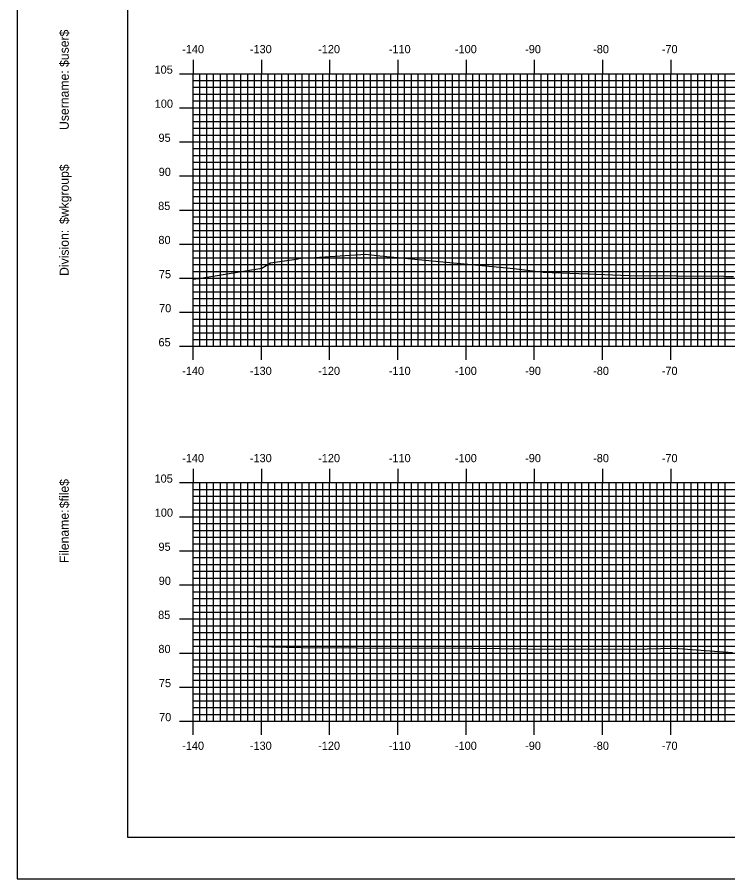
# Model space of a CAD drawing. Extents: x 857110 to 857453, y 364765 to 364985.
# Drawn here: x 857110 to 857214.2, y 364765.2 to 364891.6 of the extents above; entities that cross this region are included whole.
import ezdxf

# ---------------------------------------------------------------- set-up
doc = ezdxf.new("R2010")
doc.units = 0
for name, color, linetype in [('BORDER', 7, 'Continuous'), ('H_V ANNOTATION', 7, 'Continuous'), ('MAJOR', 7, 'Continuous'), ('MINOR', 7, 'Continuous'), ('PLOT BOUNDARY', 7, 'Continuous'), ('S_Roadway_Centerline', 7, 'Continuous')]:
    doc.layers.add(name, color=color, linetype=linetype)

msp = doc.modelspace()

# ---------------------------------------------------------------- linework, layer by layer
at = {"layer": 'BORDER'}
msp.add_lwpolyline([(857126.19, 364771.3), (857446.19, 364771.3), (857446.19, 364981.3), (857126.19, 364981.3)], close=True, dxfattribs=at)
at = {"layer": 'MAJOR'}
for p, q in [((857135.79, 364885.31), (857135.79, 364883.3)), ((857145.79, 364885.31), (857145.79, 364883.3)), ((857155.79, 364885.31), (857155.79, 364883.3)), ((857165.79, 364885.31), (857165.79, 364883.3)), ((857175.79, 364885.31), (857175.79, 364883.3)), ((857185.79, 364885.31), (857185.79, 364883.3)), ((857195.79, 364885.31), (857195.79, 364883.3)), ((857205.79, 364885.31), (857205.79, 364883.3)), ((857133.79, 364883.3), (857135.79, 364883.3)), ((857135.79, 364883.3), (857415.79, 364883.3)), ((857135.79, 364843.3), (857135.79, 364883.3)), ((857135.79, 364843.3), (857135.79, 364883.3)), ((857135.79, 364883.3), (857415.79, 364883.3)), ((857145.79, 364843.3), (857145.79, 364883.3)), ((857155.79, 364843.3), (857155.79, 364883.3)), ((857165.79, 364843.3), (857165.79, 364883.3)), ((857175.79, 364843.3), (857175.79, 364883.3)), ((857185.79, 364843.3), (857185.79, 364883.3)), ((857195.79, 364843.3), (857195.79, 364883.3)), ((857205.79, 364843.3), (857205.79, 364883.3)), ((857133.79, 364878.3), (857135.79, 364878.3)), ((857135.79, 364878.3), (857415.79, 364878.3)), ((857133.79, 364873.3), (857135.79, 364873.3)), ((857135.79, 364873.3), (857415.79, 364873.3)), ((857133.79, 364868.3), (857135.79, 364868.3)), ((857135.79, 364868.3), (857415.79, 364868.3)), ((857133.79, 364863.3), (857135.79, 364863.3)), ((857135.79, 364863.3), (857415.79, 364863.3)), ((857133.79, 364858.3), (857135.79, 364858.3)), ((857135.79, 364858.3), (857415.79, 364858.3)), ((857133.79, 364853.3), (857135.79, 364853.3)), ((857135.79, 364853.3), (857415.79, 364853.3)), ((857133.79, 364848.3), (857135.79, 364848.3)), ((857135.79, 364848.3), (857415.79, 364848.3)), ((857133.79, 364843.3), (857135.79, 364843.3)), ((857135.79, 364843.3), (857415.79, 364843.3)), ((857135.79, 364843.3), (857415.79, 364843.3)), ((857135.79, 364841.3), (857135.79, 364843.3)), ((857145.79, 364841.3), (857145.79, 364843.3)), ((857155.79, 364841.3), (857155.79, 364843.3)), ((857165.79, 364841.3), (857165.79, 364843.3)), ((857175.79, 364841.3), (857175.79, 364843.3)), ((857185.79, 364841.3), (857185.79, 364843.3)), ((857195.79, 364841.3), (857195.79, 364843.3)), ((857205.79, 364841.3), (857205.79, 364843.3)), ((857135.79, 364825.31), (857135.79, 364823.3)), ((857145.79, 364825.31), (857145.79, 364823.3)), ((857155.79, 364825.31), (857155.79, 364823.3)), ((857165.79, 364825.31), (857165.79, 364823.3)), ((857175.79, 364825.31), (857175.79, 364823.3)), ((857185.79, 364825.31), (857185.79, 364823.3)), ((857195.79, 364825.31), (857195.79, 364823.3)), ((857205.79, 364825.31), (857205.79, 364823.3)), ((857133.79, 364823.3), (857135.79, 364823.3)), ((857135.79, 364823.3), (857415.79, 364823.3)), ((857135.79, 364788.3), (857135.79, 364823.3)), ((857135.79, 364788.3), (857135.79, 364823.3)), ((857135.79, 364823.3), (857415.79, 364823.3)), ((857145.79, 364788.3), (857145.79, 364823.3)), ((857155.79, 364788.3), (857155.79, 364823.3)), ((857165.79, 364788.3), (857165.79, 364823.3)), ((857175.79, 364788.3), (857175.79, 364823.3)), ((857185.79, 364788.3), (857185.79, 364823.3)), ((857195.79, 364788.3), (857195.79, 364823.3)), ((857205.79, 364788.3), (857205.79, 364823.3)), ((857133.79, 364818.3), (857135.79, 364818.3)), ((857135.79, 364818.3), (857415.79, 364818.3)), ((857133.79, 364813.3), (857135.79, 364813.3)), ((857135.79, 364813.3), (857415.79, 364813.3)), ((857133.79, 364808.3), (857135.79, 364808.3)), ((857135.79, 364808.3), (857415.79, 364808.3)), ((857133.79, 364803.3), (857135.79, 364803.3)), ((857135.79, 364803.3), (857415.79, 364803.3)), ((857133.79, 364798.3), (857135.79, 364798.3)), ((857135.79, 364798.3), (857415.79, 364798.3)), ((857133.79, 364793.3), (857135.79, 364793.3)), ((857135.79, 364793.3), (857415.79, 364793.3)), ((857133.79, 364788.3), (857135.79, 364788.3)), ((857135.79, 364788.3), (857415.79, 364788.3)), ((857135.79, 364788.3), (857415.79, 364788.3)), ((857135.79, 364786.3), (857135.79, 364788.3)), ((857145.79, 364786.3), (857145.79, 364788.3)), ((857155.79, 364786.3), (857155.79, 364788.3)), ((857165.79, 364786.3), (857165.79, 364788.3)), ((857175.79, 364786.3), (857175.79, 364788.3)), ((857185.79, 364786.3), (857185.79, 364788.3)), ((857195.79, 364786.3), (857195.79, 364788.3)), ((857205.79, 364786.3), (857205.79, 364788.3))]:
    msp.add_line(p, q, dxfattribs=at)
at = {"layer": 'MINOR'}
for p, q in [((857136.79, 364843.3), (857136.79, 364883.3)), ((857137.79, 364843.3), (857137.79, 364883.3)), ((857138.79, 364843.3), (857138.79, 364883.3)), ((857139.79, 364843.3), (857139.79, 364883.3)), ((857140.79, 364843.3), (857140.79, 364883.3)), ((857141.79, 364843.3), (857141.79, 364883.3)), ((857142.79, 364843.3), (857142.79, 364883.3)), ((857143.79, 364843.3), (857143.79, 364883.3)), ((857144.79, 364843.3), (857144.79, 364883.3)), ((857146.79, 364843.3), (857146.79, 364883.3)), ((857147.79, 364843.3), (857147.79, 364883.3)), ((857148.79, 364843.3), (857148.79, 364883.3)), ((857149.79, 364843.3), (857149.79, 364883.3)), ((857150.79, 364843.3), (857150.79, 364883.3)), ((857151.79, 364843.3), (857151.79, 364883.3)), ((857152.79, 364843.3), (857152.79, 364883.3)), ((857153.79, 364843.3), (857153.79, 364883.3)), ((857154.79, 364843.3), (857154.79, 364883.3)), ((857156.79, 364843.3), (857156.79, 364883.3)), ((857157.79, 364843.3), (857157.79, 364883.3)), ((857158.79, 364843.3), (857158.79, 364883.3)), ((857159.79, 364843.3), (857159.79, 364883.3)), ((857160.79, 364843.3), (857160.79, 364883.3)), ((857161.79, 364843.3), (857161.79, 364883.3)), ((857162.79, 364843.3), (857162.79, 364883.3)), ((857163.79, 364843.3), (857163.79, 364883.3)), ((857164.79, 364843.3), (857164.79, 364883.3)), ((857166.79, 364843.3), (857166.79, 364883.3)), ((857167.79, 364843.3), (857167.79, 364883.3)), ((857168.79, 364843.3), (857168.79, 364883.3)), ((857169.79, 364843.3), (857169.79, 364883.3)), ((857170.79, 364843.3), (857170.79, 364883.3)), ((857171.79, 364843.3), (857171.79, 364883.3)), ((857172.79, 364843.3), (857172.79, 364883.3)), ((857173.79, 364843.3), (857173.79, 364883.3)), ((857174.79, 364843.3), (857174.79, 364883.3)), ((857176.79, 364843.3), (857176.79, 364883.3)), ((857177.79, 364843.3), (857177.79, 364883.3)), ((857178.79, 364843.3), (857178.79, 364883.3)), ((857179.79, 364843.3), (857179.79, 364883.3)), ((857180.79, 364843.3), (857180.79, 364883.3)), ((857181.79, 364843.3), (857181.79, 364883.3)), ((857182.79, 364843.3), (857182.79, 364883.3)), ((857183.79, 364843.3), (857183.79, 364883.3)), ((857184.79, 364843.3), (857184.79, 364883.3)), ((857186.79, 364843.3), (857186.79, 364883.3)), ((857187.79, 364843.3), (857187.79, 364883.3)), ((857188.79, 364843.3), (857188.79, 364883.3)), ((857189.79, 364843.3), (857189.79, 364883.3)), ((857190.79, 364843.3), (857190.79, 364883.3)), ((857191.79, 364843.3), (857191.79, 364883.3)), ((857192.79, 364843.3), (857192.79, 364883.3)), ((857193.79, 364843.3), (857193.79, 364883.3)), ((857194.79, 364843.3), (857194.79, 364883.3)), ((857196.79, 364843.3), (857196.79, 364883.3)), ((857197.79, 364843.3), (857197.79, 364883.3)), ((857198.79, 364843.3), (857198.79, 364883.3)), ((857199.79, 364843.3), (857199.79, 364883.3)), ((857200.79, 364843.3), (857200.79, 364883.3)), ((857201.79, 364843.3), (857201.79, 364883.3)), ((857202.79, 364843.3), (857202.79, 364883.3)), ((857203.79, 364843.3), (857203.79, 364883.3)), ((857204.79, 364843.3), (857204.79, 364883.3)), ((857206.79, 364843.3), (857206.79, 364883.3)), ((857207.79, 364843.3), (857207.79, 364883.3)), ((857208.79, 364843.3), (857208.79, 364883.3)), ((857209.79, 364843.3), (857209.79, 364883.3)), ((857210.79, 364843.3), (857210.79, 364883.3)), ((857211.79, 364843.3), (857211.79, 364883.3)), ((857212.79, 364843.3), (857212.79, 364883.3)), ((857213.79, 364843.3), (857213.79, 364883.3)), ((857135.79, 364882.3), (857415.79, 364882.3)), ((857135.79, 364882.3), (857137.8, 364882.3)), ((857135.79, 364881.3), (857415.79, 364881.3)), ((857135.79, 364881.3), (857137.8, 364881.3)), ((857135.79, 364880.3), (857415.79, 364880.3)), ((857135.79, 364880.3), (857137.8, 364880.3)), ((857135.79, 364879.3), (857415.79, 364879.3)), ((857135.79, 364879.3), (857137.8, 364879.3)), ((857135.79, 364877.3), (857415.79, 364877.3)), ((857135.79, 364877.3), (857137.8, 364877.3)), ((857135.79, 364876.3), (857415.79, 364876.3)), ((857135.79, 364876.3), (857137.8, 364876.3)), ((857135.79, 364875.3), (857415.79, 364875.3)), ((857135.79, 364875.3), (857137.8, 364875.3)), ((857135.79, 364874.3), (857415.79, 364874.3)), ((857135.79, 364874.3), (857137.8, 364874.3)), ((857135.79, 364872.3), (857415.79, 364872.3)), ((857135.79, 364872.3), (857137.8, 364872.3)), ((857135.79, 364871.3), (857415.79, 364871.3)), ((857135.79, 364871.3), (857137.8, 364871.3)), ((857135.79, 364870.3), (857415.79, 364870.3)), ((857135.79, 364870.3), (857137.8, 364870.3)), ((857135.79, 364869.3), (857415.79, 364869.3)), ((857135.79, 364869.3), (857137.8, 364869.3)), ((857135.79, 364867.3), (857415.79, 364867.3)), ((857135.79, 364867.3), (857137.8, 364867.3)), ((857135.79, 364866.3), (857415.79, 364866.3)), ((857135.79, 364866.3), (857137.8, 364866.3)), ((857135.79, 364865.3), (857415.79, 364865.3)), ((857135.79, 364865.3), (857137.8, 364865.3)), ((857135.79, 364864.3), (857415.79, 364864.3)), ((857135.79, 364864.3), (857137.8, 364864.3)), ((857135.79, 364862.3), (857415.79, 364862.3)), ((857135.79, 364862.3), (857137.8, 364862.3)), ((857135.79, 364861.3), (857415.79, 364861.3)), ((857135.79, 364861.3), (857137.8, 364861.3)), ((857135.79, 364860.3), (857415.79, 364860.3)), ((857135.79, 364860.3), (857137.8, 364860.3)), ((857135.79, 364859.3), (857415.79, 364859.3)), ((857135.79, 364859.3), (857137.8, 364859.3)), ((857135.79, 364857.3), (857415.79, 364857.3)), ((857135.79, 364857.3), (857137.8, 364857.3)), ((857135.79, 364856.3), (857415.79, 364856.3)), ((857135.79, 364856.3), (857137.8, 364856.3)), ((857135.79, 364855.3), (857415.79, 364855.3)), ((857135.79, 364855.3), (857137.8, 364855.3)), ((857135.79, 364854.3), (857415.79, 364854.3)), ((857135.79, 364854.3), (857137.8, 364854.3)), ((857135.79, 364852.3), (857415.79, 364852.3)), ((857135.79, 364852.3), (857137.8, 364852.3)), ((857135.79, 364851.3), (857415.79, 364851.3)), ((857135.79, 364851.3), (857137.8, 364851.3)), ((857135.79, 364850.3), (857415.79, 364850.3)), ((857135.79, 364850.3), (857137.8, 364850.3)), ((857135.79, 364849.3), (857415.79, 364849.3)), ((857135.79, 364849.3), (857137.8, 364849.3)), ((857135.79, 364847.3), (857415.79, 364847.3)), ((857135.79, 364847.3), (857137.8, 364847.3)), ((857135.79, 364846.3), (857415.79, 364846.3)), ((857135.79, 364846.3), (857137.8, 364846.3)), ((857135.79, 364845.3), (857415.79, 364845.3)), ((857135.79, 364845.3), (857137.8, 364845.3)), ((857135.79, 364844.3), (857415.79, 364844.3)), ((857135.79, 364844.3), (857137.8, 364844.3)), ((857135.79, 364822.3), (857415.79, 364822.3)), ((857135.79, 364822.3), (857137.8, 364822.3)), ((857136.79, 364788.3), (857136.79, 364823.3)), ((857137.79, 364788.3), (857137.79, 364823.3)), ((857138.79, 364788.3), (857138.79, 364823.3)), ((857139.79, 364788.3), (857139.79, 364823.3)), ((857140.79, 364788.3), (857140.79, 364823.3)), ((857141.79, 364788.3), (857141.79, 364823.3)), ((857142.79, 364788.3), (857142.79, 364823.3)), ((857143.79, 364788.3), (857143.79, 364823.3)), ((857144.79, 364788.3), (857144.79, 364823.3)), ((857146.79, 364788.3), (857146.79, 364823.3)), ((857147.79, 364788.3), (857147.79, 364823.3)), ((857148.79, 364788.3), (857148.79, 364823.3)), ((857149.79, 364788.3), (857149.79, 364823.3)), ((857150.79, 364788.3), (857150.79, 364823.3)), ((857151.79, 364788.3), (857151.79, 364823.3)), ((857152.79, 364788.3), (857152.79, 364823.3)), ((857153.79, 364788.3), (857153.79, 364823.3)), ((857154.79, 364788.3), (857154.79, 364823.3)), ((857156.79, 364788.3), (857156.79, 364823.3)), ((857157.79, 364788.3), (857157.79, 364823.3)), ((857158.79, 364788.3), (857158.79, 364823.3)), ((857159.79, 364788.3), (857159.79, 364823.3)), ((857160.79, 364788.3), (857160.79, 364823.3)), ((857161.79, 364788.3), (857161.79, 364823.3)), ((857162.79, 364788.3), (857162.79, 364823.3)), ((857163.79, 364788.3), (857163.79, 364823.3)), ((857164.79, 364788.3), (857164.79, 364823.3)), ((857166.79, 364788.3), (857166.79, 364823.3)), ((857167.79, 364788.3), (857167.79, 364823.3)), ((857168.79, 364788.3), (857168.79, 364823.3)), ((857169.79, 364788.3), (857169.79, 364823.3)), ((857170.79, 364788.3), (857170.79, 364823.3)), ((857171.79, 364788.3), (857171.79, 364823.3)), ((857172.79, 364788.3), (857172.79, 364823.3)), ((857173.79, 364788.3), (857173.79, 364823.3)), ((857174.79, 364788.3), (857174.79, 364823.3)), ((857176.79, 364788.3), (857176.79, 364823.3)), ((857177.79, 364788.3), (857177.79, 364823.3)), ((857178.79, 364788.3), (857178.79, 364823.3)), ((857179.79, 364788.3), (857179.79, 364823.3)), ((857180.79, 364788.3), (857180.79, 364823.3)), ((857181.79, 364788.3), (857181.79, 364823.3)), ((857182.79, 364788.3), (857182.79, 364823.3)), ((857183.79, 364788.3), (857183.79, 364823.3)), ((857184.79, 364788.3), (857184.79, 364823.3)), ((857186.79, 364788.3), (857186.79, 364823.3)), ((857187.79, 364788.3), (857187.79, 364823.3)), ((857188.79, 364788.3), (857188.79, 364823.3)), ((857189.79, 364788.3), (857189.79, 364823.3)), ((857190.79, 364788.3), (857190.79, 364823.3)), ((857191.79, 364788.3), (857191.79, 364823.3)), ((857192.79, 364788.3), (857192.79, 364823.3)), ((857193.79, 364788.3), (857193.79, 364823.3)), ((857194.79, 364788.3), (857194.79, 364823.3)), ((857196.79, 364788.3), (857196.79, 364823.3)), ((857197.79, 364788.3), (857197.79, 364823.3)), ((857198.79, 364788.3), (857198.79, 364823.3)), ((857199.79, 364788.3), (857199.79, 364823.3)), ((857200.79, 364788.3), (857200.79, 364823.3)), ((857201.79, 364788.3), (857201.79, 364823.3)), ((857202.79, 364788.3), (857202.79, 364823.3)), ((857203.79, 364788.3), (857203.79, 364823.3)), ((857204.79, 364788.3), (857204.79, 364823.3)), ((857206.79, 364788.3), (857206.79, 364823.3)), ((857207.79, 364788.3), (857207.79, 364823.3)), ((857208.79, 364788.3), (857208.79, 364823.3)), ((857209.79, 364788.3), (857209.79, 364823.3)), ((857210.79, 364788.3), (857210.79, 364823.3)), ((857211.79, 364788.3), (857211.79, 364823.3)), ((857212.79, 364788.3), (857212.79, 364823.3)), ((857213.79, 364788.3), (857213.79, 364823.3)), ((857135.79, 364821.3), (857415.79, 364821.3)), ((857135.79, 364821.3), (857137.8, 364821.3)), ((857135.79, 364820.3), (857415.79, 364820.3)), ((857135.79, 364820.3), (857137.8, 364820.3)), ((857135.79, 364819.3), (857415.79, 364819.3)), ((857135.79, 364819.3), (857137.8, 364819.3)), ((857135.79, 364817.3), (857415.79, 364817.3)), ((857135.79, 364817.3), (857137.8, 364817.3)), ((857135.79, 364816.3), (857415.79, 364816.3)), ((857135.79, 364816.3), (857137.8, 364816.3)), ((857135.79, 364815.3), (857415.79, 364815.3)), ((857135.79, 364815.3), (857137.8, 364815.3)), ((857135.79, 364814.3), (857415.79, 364814.3)), ((857135.79, 364814.3), (857137.8, 364814.3)), ((857135.79, 364812.3), (857415.79, 364812.3)), ((857135.79, 364812.3), (857137.8, 364812.3)), ((857135.79, 364811.3), (857137.8, 364811.3)), ((857135.79, 364811.3), (857415.79, 364811.3)), ((857135.79, 364810.3), (857137.8, 364810.3)), ((857135.79, 364810.3), (857415.79, 364810.3)), ((857135.79, 364809.3), (857415.79, 364809.3)), ((857135.79, 364809.3), (857137.8, 364809.3)), ((857135.79, 364807.3), (857415.79, 364807.3)), ((857135.79, 364807.3), (857137.8, 364807.3)), ((857135.79, 364806.3), (857415.79, 364806.3)), ((857135.79, 364806.3), (857137.8, 364806.3)), ((857135.79, 364805.3), (857415.79, 364805.3)), ((857135.79, 364805.3), (857137.8, 364805.3)), ((857135.79, 364804.3), (857415.79, 364804.3)), ((857135.79, 364804.3), (857137.8, 364804.3)), ((857135.79, 364802.3), (857415.79, 364802.3)), ((857135.79, 364802.3), (857137.8, 364802.3)), ((857135.79, 364801.3), (857415.79, 364801.3)), ((857135.79, 364801.3), (857137.8, 364801.3)), ((857135.79, 364800.3), (857415.79, 364800.3)), ((857135.79, 364800.3), (857137.8, 364800.3)), ((857135.79, 364799.3), (857415.79, 364799.3)), ((857135.79, 364799.3), (857137.8, 364799.3)), ((857135.79, 364797.3), (857415.79, 364797.3)), ((857135.79, 364797.3), (857137.8, 364797.3)), ((857135.79, 364796.3), (857415.79, 364796.3)), ((857135.79, 364796.3), (857137.8, 364796.3)), ((857135.79, 364795.3), (857415.79, 364795.3)), ((857135.79, 364795.3), (857137.8, 364795.3)), ((857135.79, 364794.3), (857415.79, 364794.3)), ((857135.79, 364794.3), (857137.8, 364794.3)), ((857135.79, 364792.3), (857415.79, 364792.3)), ((857135.79, 364792.3), (857137.8, 364792.3)), ((857135.79, 364791.3), (857415.79, 364791.3)), ((857135.79, 364791.3), (857137.8, 364791.3)), ((857135.79, 364790.3), (857415.79, 364790.3)), ((857135.79, 364790.3), (857137.8, 364790.3)), ((857135.79, 364789.3), (857415.79, 364789.3)), ((857135.79, 364789.3), (857137.8, 364789.3))]:
    msp.add_line(p, q, dxfattribs=at)
at = {"layer": 'PLOT BOUNDARY'}
msp.add_lwpolyline([(857110.01, 364765.18), (857450.01, 364765.18), (857450.01, 364985.18), (857110.01, 364985.18)], close=True, dxfattribs=at)
at = {"layer": 'S_Roadway_Centerline'}
for points in [[(857135.79, 364853.15), (857136.61, 364853.26), (857136.85, 364853.28), (857137.23, 364853.34), (857145.84, 364854.78), (857147.11, 364855.54), (857150.89, 364856.11), (857151.57, 364856.24), (857153.56, 364856.34), (857161.12, 364856.82), (857163.17, 364856.58), (857172.37, 364855.72), (857182.8, 364854.72), (857187.11, 364854.19), (857193.63, 364853.92), (857199.71, 364853.68), (857213.59, 364853.58), (857213.93, 364853.55), (857215.01, 364853.53)], [(857135.79, 364799.36), (857142.95, 364799.3), (857151.64, 364799.13), (857159.77, 364799.08), (857165.97, 364799.01), (857172.59, 364799.08), (857184.77, 364798.94), (857200.37, 364798.89), (857206.28, 364799.02), (857214.84, 364798.4)]]:
    msp.add_lwpolyline(points, dxfattribs=at)

# ---------------------------------------------------------------- texts
at = {"layer": 'BORDER'}
for s, p in [('$user$', (857117.56, 364884.29)), ('Username:', (857117.56, 364875.04)), ('$wkgroup$', (857117.56, 364861.24)), ('Division:', (857117.56, 364853.63)), ('$file$', (857117.56, 364819.55)), ('Filename:', (857117.56, 364811.5))]:
    msp.add_text(s, height=1.339, rotation=90, dxfattribs=at).set_placement(p)
at = {"layer": 'H_V ANNOTATION'}
for s, p in [('-140', (857134.18, 364886.3)), ('-130', (857144.1, 364886.3)), ('-120', (857154.11, 364886.3)), ('-110', (857164.46, 364886.3)), ('-100', (857174.16, 364886.3)), ('-90', (857184.45, 364886.3)), ('-80', (857194.42, 364886.3)), ('-70', (857204.48, 364886.3)), ('105', (857130.13, 364883.3)), ('100', (857130.16, 364878.3)), ('95', (857130.71, 364873.3)), ('90', (857130.74, 364868.3)), ('85', (857130.66, 364863.3)), ('80', (857130.7, 364858.3)), ('75', (857130.77, 364853.3)), ('70', (857130.8, 364848.3)), ('65', (857130.71, 364843.3)), ('-140', (857134.18, 364839.1)), ('-130', (857144.1, 364839.1)), ('-120', (857154.11, 364839.1)), ('-110', (857164.46, 364839.1)), ('-100', (857174.16, 364839.1)), ('-90', (857184.45, 364839.1)), ('-80', (857194.42, 364839.1)), ('-70', (857204.48, 364839.1)), ('-140', (857134.18, 364826.3)), ('-130', (857144.1, 364826.3)), ('-120', (857154.11, 364826.3)), ('-110', (857164.46, 364826.3)), ('-100', (857174.16, 364826.3)), ('-90', (857184.45, 364826.3)), ('-80', (857194.42, 364826.3)), ('-70', (857204.48, 364826.3)), ('105', (857130.13, 364823.3)), ('100', (857130.16, 364818.3)), ('95', (857130.71, 364813.3)), ('90', (857130.74, 364808.3)), ('85', (857130.66, 364803.3)), ('80', (857130.7, 364798.3)), ('75', (857130.77, 364793.3)), ('70', (857130.8, 364788.3)), ('-140', (857134.18, 364784.1)), ('-130', (857144.1, 364784.1)), ('-120', (857154.11, 364784.1)), ('-110', (857164.46, 364784.1)), ('-100', (857174.16, 364784.1)), ('-90', (857184.45, 364784.1)), ('-80', (857194.42, 364784.1)), ('-70', (857204.48, 364784.1))]:
    msp.add_text(s, height=1.2, dxfattribs=at).set_placement(p)
at = {"layer": 'MAJOR'}
for p in [(857135.79, 364843.3), (857135.79, 364788.3)]:
    msp.add_text('-', height=0.012, dxfattribs=at).set_placement(p)

doc.saveas('drawing.dxf')
